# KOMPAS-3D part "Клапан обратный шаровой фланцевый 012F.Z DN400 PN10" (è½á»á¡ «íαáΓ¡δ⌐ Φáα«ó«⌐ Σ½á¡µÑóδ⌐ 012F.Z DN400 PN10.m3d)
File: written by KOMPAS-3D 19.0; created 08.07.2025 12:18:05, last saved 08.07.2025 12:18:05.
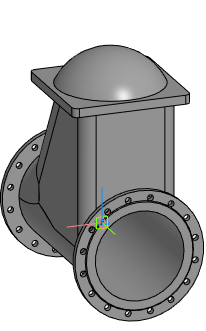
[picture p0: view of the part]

Document properties: Полное имя файла: E:\Dendor Работа Сачек\3D для проектировщиков\5.3 Тип 012F, 012F.Z Клапан обратный шаровой фланцевый\stp_Клапан обратный шаровой фланцевый 012F.Z PN10_16\Клапан обратный шаровой фланцевый 012F.Z DN400 PN10.m3d

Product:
- Part/product: Клапан обратный шаровой фланцевый 012F.Z DN400 PN10

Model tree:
1. Операция без истории:1  (labels: Клапан обратный шаровой фланцевый 012F.Z DN400 PN10)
